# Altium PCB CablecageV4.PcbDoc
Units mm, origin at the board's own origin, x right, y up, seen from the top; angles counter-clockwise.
Board outline 44.5 x 40.08 mm, 2 copper layers (Top Layer, Bottom Layer); 20 components, 28 nets, 91 pads, 70 vias.
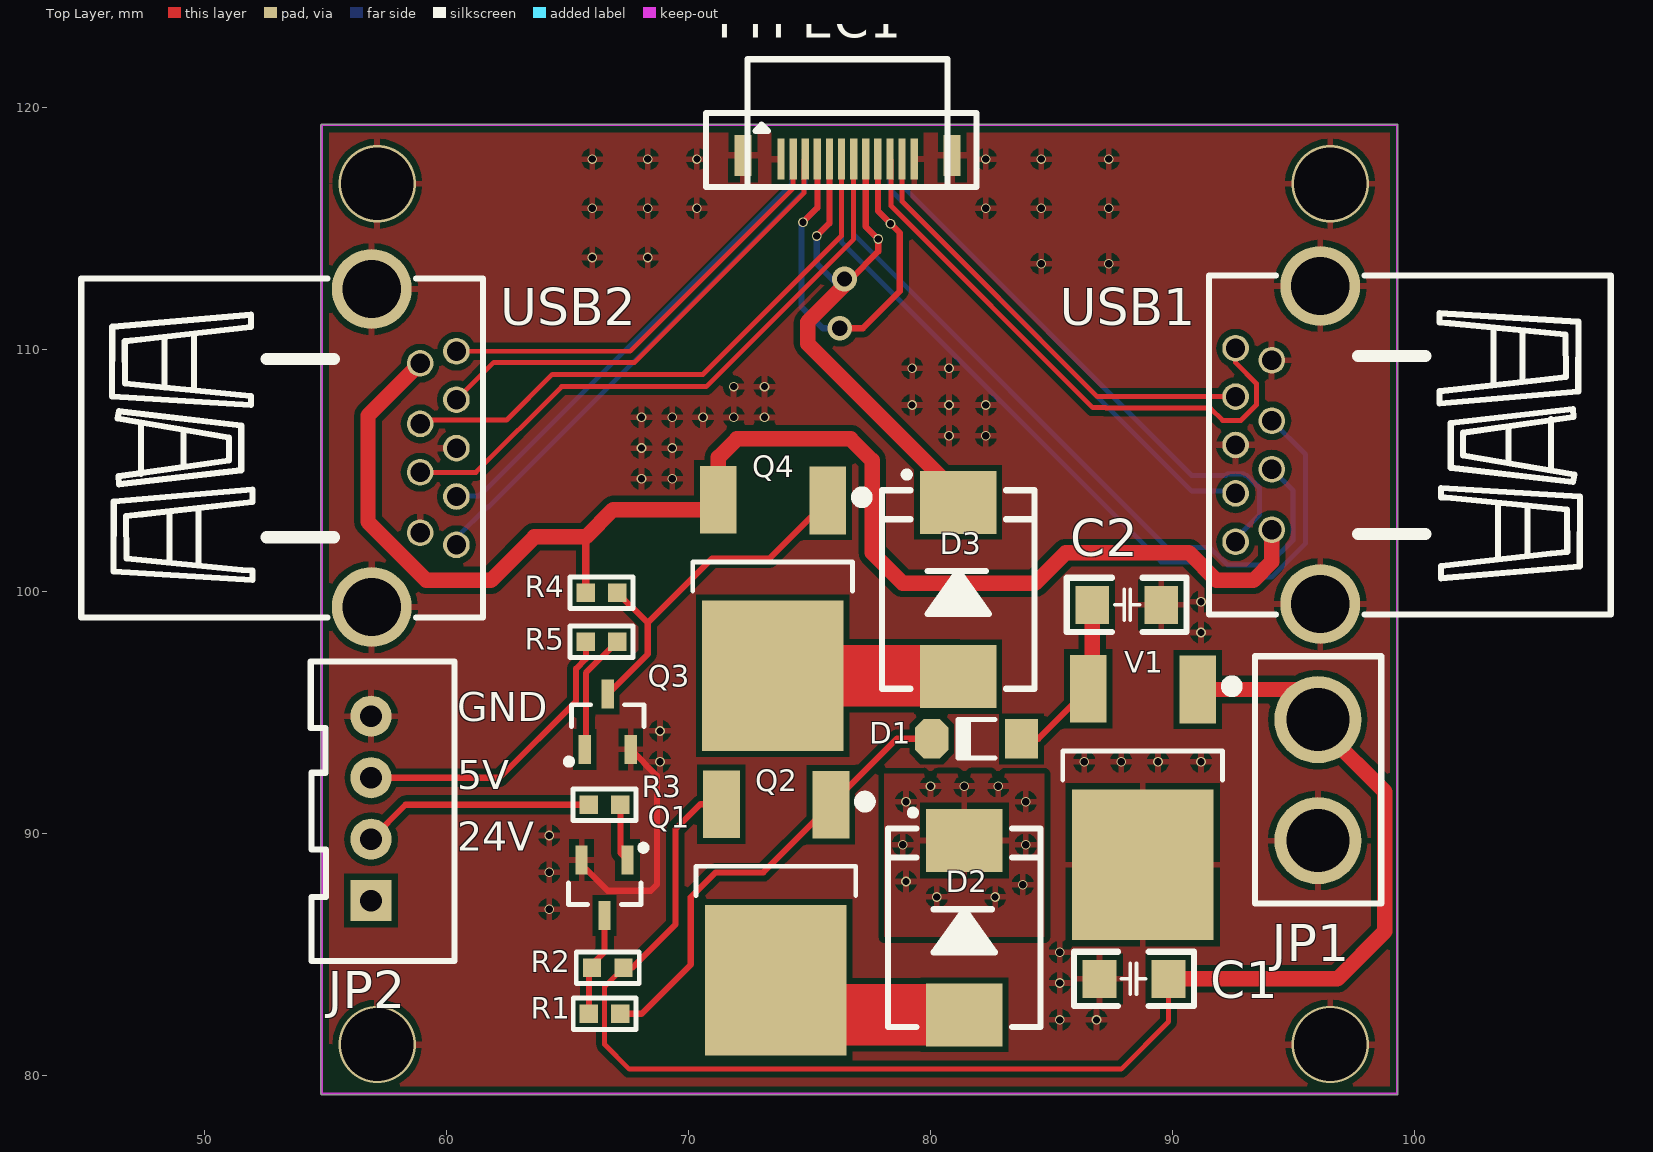
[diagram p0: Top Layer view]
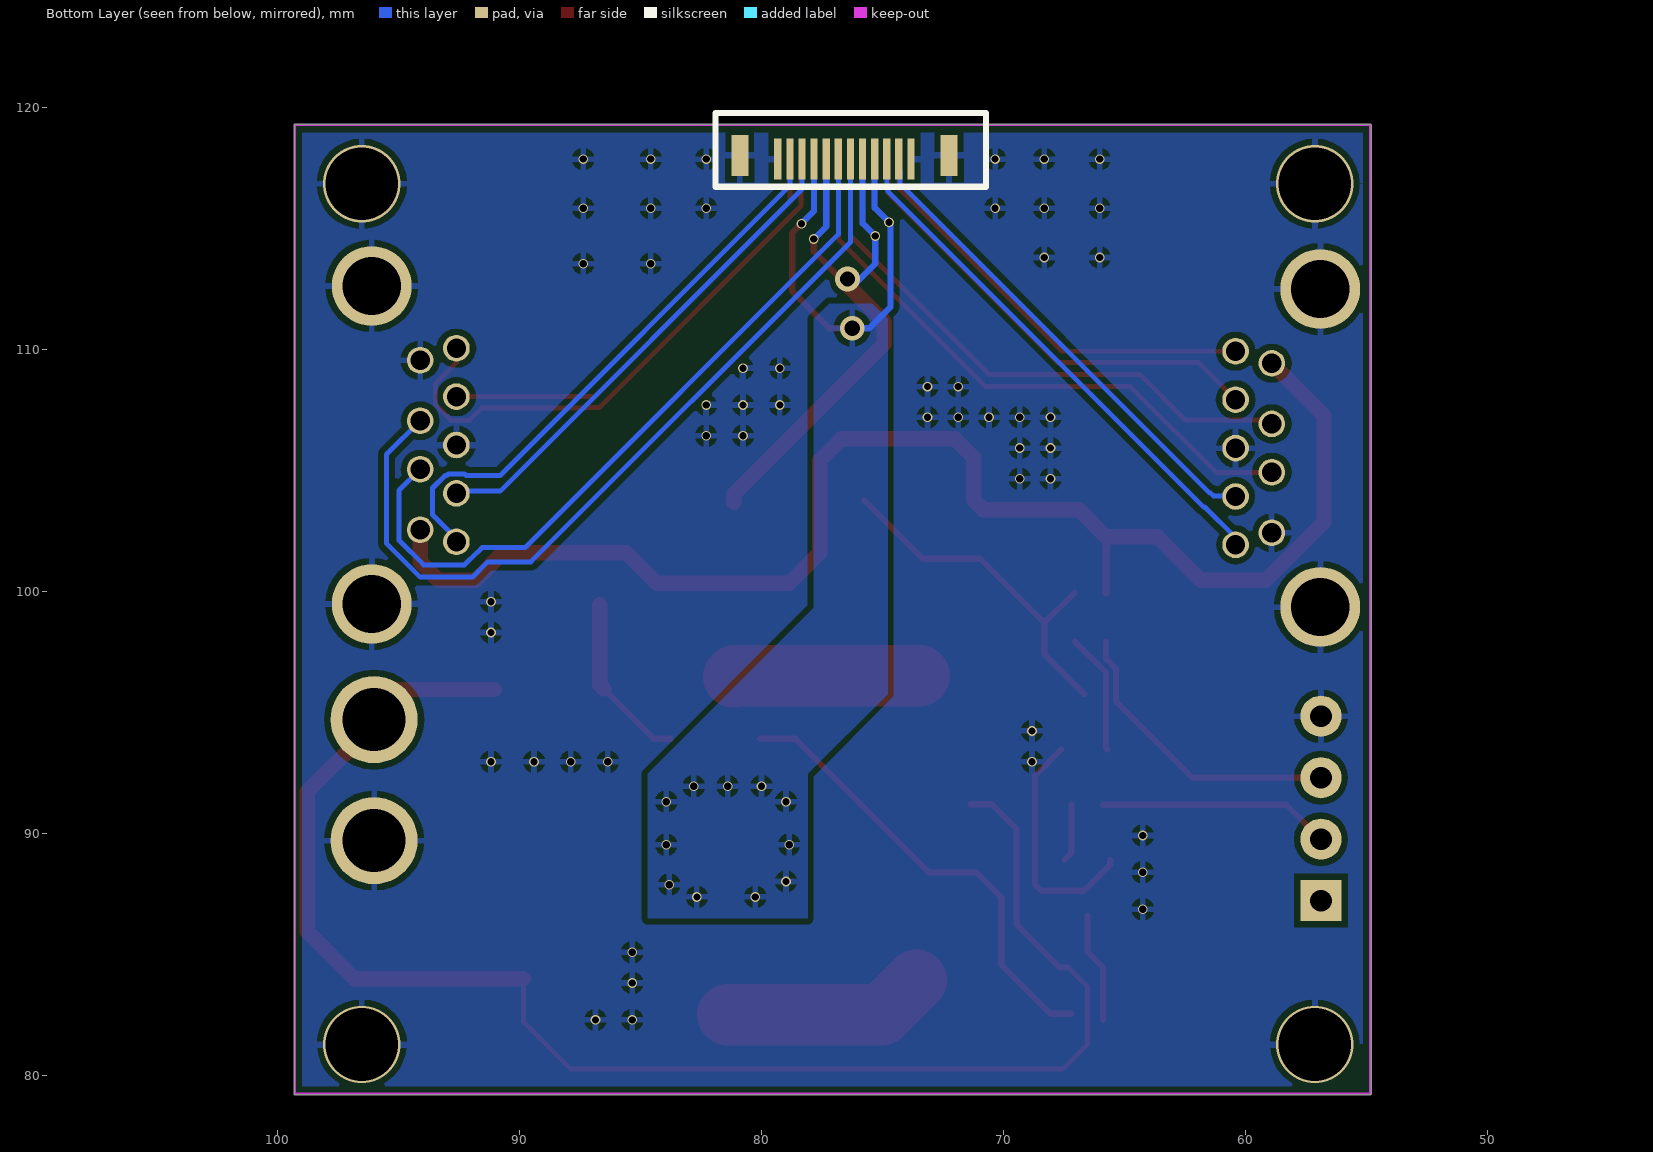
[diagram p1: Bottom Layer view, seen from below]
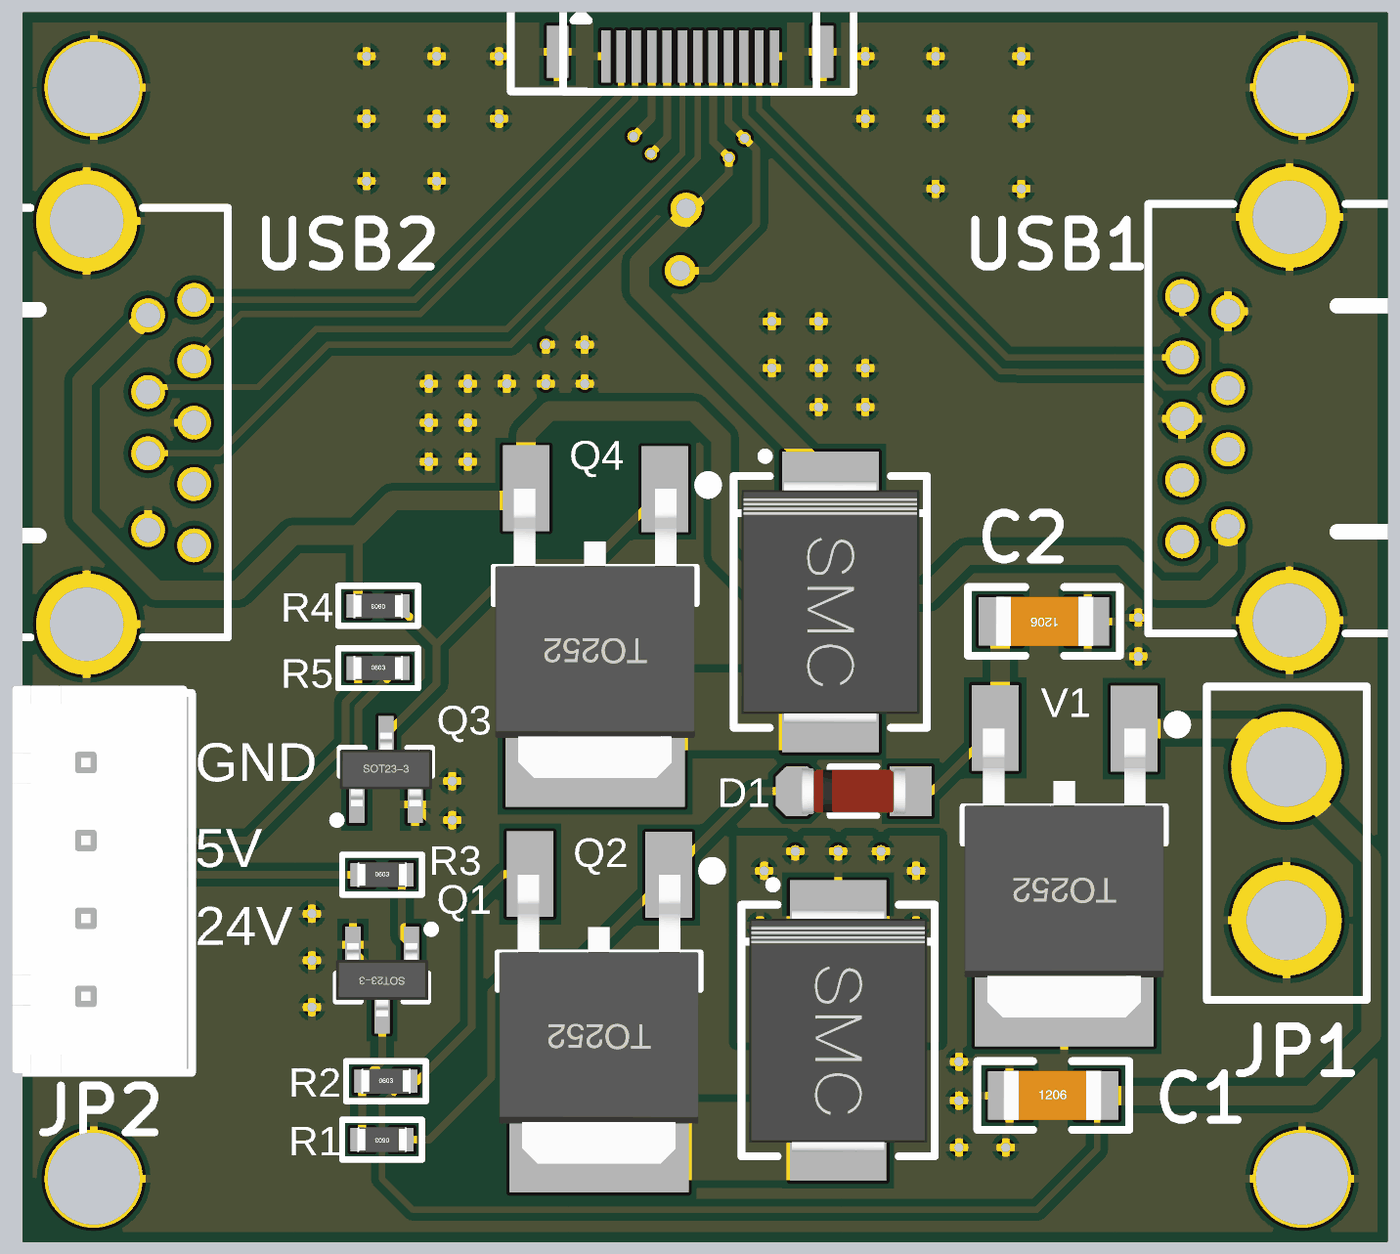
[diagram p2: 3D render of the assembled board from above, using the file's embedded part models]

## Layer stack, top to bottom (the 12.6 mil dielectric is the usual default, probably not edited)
Top Solder: solder mask 0.0102, Solder Resist, Dk 3.5
Top Layer: signal copper 0.0356
Dielectric 1: dielectric 0.32, FR-4, Dk 4.8
Bottom Layer: signal copper 0.0356
Bottom Solder: solder mask 0.0102, Solder Resist, Dk 3.5

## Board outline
54.864,79.21 cw(c54.864,79.248) 54.826,79.248 54.826,119.253 cw(c54.864,119.253) 54.864,119.291 99.282,119.291 cw(c99.282,119.253) 99.321,119.253 99.321,79.248 cw(c99.282,79.248) 99.282,79.21

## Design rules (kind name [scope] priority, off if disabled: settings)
Clearance [All] p1: gap=0.152 ignorepadtopadclearanceinfootprint=TRUE except(0: Arc-Hole Track-Hole SMDPad-Hole THPad-Hole Via-Hole Fill-Hole Poly-Hole Region-Hole Text-Hole; 0.254: Arc-Fill Arc-Poly Arc-Region Track-Fill Track-Poly Track-Region SMDPad-Fill SMDPad-Poly SMDPad-Region THPad-Fill THPad-Poly THPad-Region Via-Fill Via-Poly Via-Region Fill-Fill Fill-Poly Fill-Region Poly-Poly Poly-Region Region-Region)
DiffPairsRouting [All] p1: maxlimit=0.508 minlimit=0.254 mostfreqgap=0.381 toplayer_minwidth=0.152 toplayer_maxwidth=0.635 toplayer_prefwidth=0.381 bottomlayer_minwidth=0.152 bottomlayer_maxwidth=0.635 bottomlayer_prefwidth=0.381 maxuncoupledlength=12.7
PolygonConnect [All] p1: connectstyle=Relief reliefconductorwidth=0.254 reliefentries=4 polygonreliefangle="90 Angle" airgapwidth=0.254
RoutingVias [All] p1: holewidth=0.711 width=1.27 viastyle="Through Hole" minholewidth=0.711 minwidth=1.27 maxholewidth=0.711 maxwidth=1.27
SolderMaskExpansion [All] p1: expansion=0.102
Width [All] p1: maxlimit=2.54 minlimit=0.152 preferedwidth=0.254 minimp=50.000000 maximp=50.000000 favimp=50.000000
29 further rules are at their usual default settings.

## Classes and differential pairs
differential pair D4: +D4_P -D4_N
differential pair USB3-T: +USB3-T_P -USB3-T_N
differential pair USB3-T2: +USB3-T2_P -USB3-T2_N
differential pair USB3-R: +USB3-R_P -USB3-R_N
differential pair USB3-R2: +USB3-R2_P -USB3-R2_N
differential pair D3: +D3_P -D3_N

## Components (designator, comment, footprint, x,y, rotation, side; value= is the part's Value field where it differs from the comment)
C1 "104" "C 1206_L" 88.392,83.991 r0 top
C2 "104" "C 1206_L" 88.138,99.441 r180 top
D1 "1N4148" "MINI_MELF (LL34)" 81.915,93.909 r180 top
D2 "SS34" SMC 81.407,86.106 r90 top
D3 "SS34" SMC 81.153,100.076 r90 top
JP1 "HDR-1X2" XT30 96.012,92.202 r270 top
JP2 "HDR-1X4" XH2.54-LI-4P 56.896,91.032 r90 top
Q1 "SI2302" SOT23-3N 66.548,87.757 r180 top
Q2 "IRF540" TO252 73.616,88.138 r180 top
Q3 "SI2302" SOT23-3N 66.675,94.615 r0 top
Q4 "IRF540" TO252 73.489,100.711 r180 top
R1 "1K" "R 0603_L" 66.548,82.55 r180 top
R2 "1K" "R 0603_L" 66.675,84.455 r0 top
R3 "1K" "R 0603_L" 66.548,91.186 r0 top
R4 "1K" "R 0603_L" 66.421,99.949 r180 top
R5 "1K" "R 0603_L" 66.421,97.917 r0 top
TYPEC1 "USB31-TYPEC-33141-2FS" TYPEC-CHABAN24P 76.581,116.713 r90 top
USB1 "FUS301-FDBU1K" USB3.0-A-TH_FUS301-FDBU1K 94.361,106.045 r90 top
USB2 "FUS301-FDBU1K" USB3.0-A-TH_FUS301-FDBU1K 58.674,105.918 r270 top
V1 "78xx" TO252 88.773,92.903 r180 top

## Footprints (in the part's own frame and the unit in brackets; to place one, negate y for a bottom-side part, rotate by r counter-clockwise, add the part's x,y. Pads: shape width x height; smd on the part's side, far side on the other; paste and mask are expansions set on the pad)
"C 1206_L" [mil] "无极性贴片电容"
  rect 55x62 smd: 1(-55.12,0) 2(57.09,0)
  silkscreen extent -96,-44 98,44, body extent -63,-32 63,32, height 48
"MINI_MELF (LL34)" [mm] "1.5*3.4mm(直径，脚距）"
  rect 1.37x1.62 smd: 1(-1.855,0)
  oct 1.37x1.62 smd: 2(1.855,0)
  silkscreen extent -0.76,-0.8 0.78,0.8, body extent -1.7,-0.75 1.7,0.75, height 1.5
"R 0603_L" [mil] "1/10W贴片电阻                 淘宝ID:黄晶宝石"
  rect 30x30 smd: 1(-25.59,0) 2(25.59,0)
  silkscreen extent -51,-26 51,26, body extent -31,-16 32,16, height 16
SMC [mm] "7.1x5.9*2.3mm（长宽高，不包括引脚）"
  rect 2.6x3.15 smd: 1(-3.6,0) 2(3.6,0)
  silkscreen extent -4.1,-3.15 4.87,3.15, body extent -3.95,-2.9 3.95,2.9, height 2.45
SOT23-3N [mm] "3x1.3x1mm(长宽高)    封装库来自淘宝卖家 ID：黄晶宝石"
  rect 0.5x1.2 smd: 1(-0.95,-1.143) 2(0.95,-1.143) 3(0,1.143)
  silkscreen extent -1.73,-1.78 1.5,0.7, body extent -1.5,-1.2 1.5,1.2, height 1.05
TO252 [mil] "252晶体管"
  rect 60x110 smd: 1(-89.55,-119.77) 3(88.45,-120.77)
  rect 230x245 smd: 2(0,165.35)
  silkscreen extent -153,-133 130,28, body extent -128,-120 128,251, height 91
TYPEC-CHABAN24P [mm]
  rect 1.7x0.7 smd: 0(1.293,4.317) 0(1.293,-4.323)
  rect 1.7x0.7 smd far side: 0(1.293,4.317) 0(1.293,-4.323)
  rect 1.7x0.3 smd: A1(1.143,2.747) A2(1.143,2.248) A3(1.143,1.748) A4(1.143,1.247) A5(1.143,0.746) A6(1.143,0.247) A7(1.143,-0.253) A8(1.143,-0.752) A9(1.143,-1.252) A10(1.143,-1.751) A11(1.143,-2.252) A12(1.143,-2.753)
  rect 1.7x0.3 smd far side: B1(1.143,-2.753) B2(1.143,-2.253) B3(1.143,-1.753) B4(1.143,-1.254) B5(1.143,-0.754) B6(1.143,-0.254) B7(1.143,0.247) B8(1.143,0.748) B9(1.143,1.248) B10(1.143,1.748) B11(1.143,2.247) B12(1.143,2.747)
  silkscreen extent -0.01,-5.33 5.27,5.84
USB3.0-A-TH_FUS301-FDBU1K [mm]
  round 1.1 hole 0.8: 1(-3.5,0.25) 2(-1,0.25) 3(1,0.25) 4(3.5,0.25) 5(4,1.75) 6(2,1.75) 7(0,1.75) 8(-2,1.75) 9(-4,1.75)
  round 3.3 hole 2.4: 10(-6.57,-1.75) 10(6.57,-1.75)
  silkscreen extent -7,-13.75 7,2.85
XH2.54-LI-4P [mm] "接插件，4P  淘宝ID:黄晶宝石   店铺网址:https://shop463601444.taobao.com"
  rect 1.7x1.7 hole 0.9: 1(-3.81,0)
  round 1.7 hole 0.9: 2(-1.27,0) 3(1.27,0) 4(3.81,0)
  silkscreen extent -6.3,-3.45 6.07,2.49, body extent -6.31,-3.3 6.31,2.4, height 7.03
XT30 [mm]
  round 3.6 hole 2.6: 1(-2.5,0) 2(2.5,0)
  silkscreen extent -5.12,-2.59 5.09,2.62

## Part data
C1 C2: library part C, "贴片电容"
D1: "开关二极管"
D2 D3: "肖特基二极管"
JP1: library part "Header 2", "2P接插件"
JP2: library part "Header 4", "4P接插件"
Q1 Q3: "N沟道场效应管"
Q2 Q4: "P沟场效应管"
R1 R2 R3 R4 R5: library part R, "贴片电阻"
TYPEC1: BOM_JLCPCB Part Class="Extended Part", BOM_Manufacturer="XKB Enterprise"
USB1 USB2: BOM_JLCPCB Part Class="Extended Part", BOM_Manufacturer=TXGA
V1: "线性稳压芯片"

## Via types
v1: diameter 0.4, hole 0.3, Top Layer to Bottom Layer, 64 vias
v2: diameter 3.2, hole 3, Top Layer to Bottom Layer, 4 vias
v3: diameter 1.016, hole 0.635, Top Layer to Bottom Layer, 2 vias

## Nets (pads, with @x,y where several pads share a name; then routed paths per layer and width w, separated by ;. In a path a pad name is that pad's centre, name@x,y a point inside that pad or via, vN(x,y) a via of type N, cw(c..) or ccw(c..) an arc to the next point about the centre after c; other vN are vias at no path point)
3V3: JP2.1
5.0V: D3.2 TYPEC1.A5 TYPEC1.A8 TYPEC1.B5 TYPEC1.B8 | length 31.4
  Top Layer w0.254: v1(75.311,114.681) 75.835,115.205 TYPEC1.A5 ; v3(76.454,112.903) 76.708,112.903 77.851,114.046 v1(77.851,114.554) 77.333,115.072 TYPEC1.A8
  Top Layer w0.635: v3(76.454,112.903) 76.454,112.649 74.93,111.125 74.93,110.236 81.153,104.013 D3.2
  Bottom Layer w0.254: TYPEC1.B8 75.833,115.203 v1(75.311,114.681) 75.311,113.538 76.2,112.649 v3(76.454,112.903) ; TYPEC1.B5 77.335,115.07 v1(77.851,114.554)
5V: Q4.3 R4.2 USB1.1 USB2.1 | length 58.9
  Top Layer w0.305: R4.2 65.771,102.25
  Top Layer w0.635: USB2.1 56.769,107.263 56.769,102.87 59.182,100.457 61.849,100.457 63.642,102.25 65.771,102.25 66.899,103.378 70.842,103.378 Q4.3 71.242,105.532 72.009,106.299 76.708,106.299 77.597,105.41 77.597,101.6 78.867,100.33 84.328,100.33 85.598,101.6 90.678,101.6 91.821,100.457 93.345,100.457 94.111,101.223 USB1.1
9V: C2.2 D1.1 V1.3 | length 7.1
  Top Layer w0.254: D1.1 84.464,93.909 V1.3
  Top Layer w0.635: V1.3 86.688,96.132 C2.2
24V: C1.2 JP1.1 Q2.3 R2.2 V1.1 | length 64.2
  Top Layer w0.203: R2.2 66.548,83.678 66.548,81.28 67.564,80.264 87.884,80.264 89.842,82.222 C1.2
  Top Layer w0.254: R2.2 67.691,84.455 69.469,86.233 69.469,90.17 70.505,91.206 Q2.3
  Top Layer w0.635: C1.2 96.818,83.991 98.774,85.947 98.774,91.726 96.393,94.107 96.393,94.575 95.023,95.945 V1.1
D3_N: TYPEC1.A7 USB2.3 | length 25.2
  Top Layer w0.203: USB2.3 61.228,104.918 64.768,108.458 70.739,108.458 76.834,114.553 TYPEC1.A7
D3_P: TYPEC1.A6 USB2.2 | length 23.8
  Top Layer w0.203: USB2.2 59.084,107.078 62.501,107.078 64.389,108.966 70.612,108.966 76.334,114.688 TYPEC1.A6
D4_N: TYPEC1.B7 USB1.3 | length 34.6
  Bottom Layer w0.203: TYPEC1.B7 76.334,114.42 89.535,101.219 91.313,101.219 91.948,100.584 94.107,100.584 95.504,101.981 95.504,105.652 USB1.3
D4_P: TYPEC1.B6 USB1.2 | length 30.6
  Bottom Layer w0.203: TYPEC1.B6 76.835,114.745 89.777,101.803 91.555,101.803 91.758,101.6 91.77,101.6 92.278,101.092 93.968,101.092 94.984,102.108 94.984,104.172 USB1.2
GATE_5V: Q3.3 Q4.1 R4.1 | length 14.9
  Top Layer w0.254: Q3.3 68.326,97.409 68.326,98.694 ; R4.1 68.326,98.694 ; Q4.1 73.356,101.346 70.978,101.346 68.326,98.694
GATE_24V: D1.2 Q2.1 R1.1 | length 19.2
  Top Layer w0.254: R1.1 68.072,82.55 70.104,84.582 70.104,87.361 71.135,88.392 73.102,88.392 Q2.1 78.619,93.909 D1.2
GND: C1.1 C2.1 JP1.2 JP2.4 Q1.2 Q3.2 TYPEC1.0 TYPEC1.A1 TYPEC1.A12 TYPEC1.B1 TYPEC1.B12 USB1.4 USB1.7 USB1.10 USB2.4 USB2.7 USB2.10 V1.2 | length 9.9
  Top Layer w0.254: Q1.2 65.598,88.707 66.675,87.63 68.453,87.63 68.707,87.884 68.707,92.39 Q3.2
  other v1: 85.344,82.296 86.868,82.296 85.344,83.82 85.344,85.09 64.262,86.868 64.262,88.392 64.262,89.916 68.834,92.964 86.36,92.964 87.884,92.964 89.408,92.964 91.186,92.964 68.834,94.234 91.186,98.298 91.186,99.568 68.072,104.648 69.342,104.648 68.072,105.918 69.342,105.918 80.772,106.426 82.296,106.426 68.072,107.188 69.342,107.188 70.612,107.188 71.882,107.188 73.152,107.188 79.248,107.696 80.772,107.696 82.296,107.696 71.882,108.458 73.152,108.458 79.248,109.22 80.772,109.22 84.582,113.538 87.376,113.538 66.04,113.792 68.326,113.792 66.04,115.824 68.326,115.824 70.358,115.824 82.296,115.824 84.582,115.824 87.376,115.824 66.04,117.856 68.326,117.856 70.358,117.856 82.296,117.856 84.582,117.856 87.376,117.856
  other v2: 57.15,81.28 96.52,81.28 57.15,116.84 96.52,116.84
NetD2_1: D2.1 Q2.2 | length 8.4
  Top Layer w2.54: Q2.2 75.048,82.506 D2.1
NetD3_1: D3.1 Q4.2 | length 7.7
  Top Layer w2.54: Q4.2 81.118,96.511 D3.1
NetQ1_1: Q1.1 R3.2 | length 2.4
  Top Layer w0.254: R3.2 67.198,89.2 Q1.1
NetQ1_3: Q1.3 R1.2 R2.1 | length 4.6
  Top Layer w0.254: R1.2@65.898,82.296 65.898,84.455 66.548,85.105 Q1.3
NetQ3_1: Q3.1 R5.2 | length 5
  Top Layer w0.254: Q3.1 65.771,93.518 65.771,96.632 R5.2@67.063,97.924
USB3-R2_N: TYPEC1.A10 USB1.5 | length 23.7
  Top Layer w0.203: TYPEC1.A10 78.376,117.812 78.376,115.923 86.711,107.588 87.249,107.588 87.249,107.569 91.567,107.569 92.075,107.061 92.837,107.061 93.472,107.696 93.472,108.585 92.611,109.446 USB1.5
USB3-R2_P: TYPEC1.A11 USB1.6 | length 18.9
  Top Layer w0.203: TYPEC1.A11 78.833,116.112 86.9,108.045 USB1.6
USB3-R_N: TYPEC1.B10 USB2.5 | length 21.9
  Bottom Layer w0.203: USB2.5 60.424,102.207 61.706,103.489 61.757,103.489 74.791,116.523 74.791,116.574 74.833,116.616 TYPEC1.B10
USB3-R_P: TYPEC1.B11 USB2.6 | length 20.3
  Bottom Layer w0.203: USB2.6 60.424,103.946 61.337,103.946 61.464,104.073 61.515,104.073 74.295,116.853 74.295,117.357 74.334,117.395 TYPEC1.B11
USB3-T2_N: TYPEC1.B3 USB1.8 | length 20.7
  Bottom Layer w0.203: TYPEC1.B3 78.334,116.611 90.805,104.14 92.516,104.14 USB1.8
USB3-T2_P: TYPEC1.B2 USB1.9 | length 23.7
  Bottom Layer w0.203: TYPEC1.B2 78.834,116.757 90.811,104.781 92.21,104.781 92.278,104.849 92.944,104.849 93.012,104.781 93.085,104.781 93.599,104.267 93.599,103.17 92.611,102.182 USB1.9
USB3-T_N: TYPEC1.A3 USB2.8 | length 19.3
  Top Layer w0.203: USB2.8 61.967,109.461 67.79,109.461 74.79,116.461 74.79,117.814 TYPEC1.A3
USB3-T_P: TYPEC1.A2 USB2.9 | length 17.9
  Top Layer w0.203: USB2.9 67.601,109.918 74.333,116.65 TYPEC1.A2
VCC: D2.2 TYPEC1.A4 TYPEC1.A9 TYPEC1.B4 TYPEC1.B9 | length 23
  Top Layer w0.254: v1(74.739,115.252) 75.334,115.847 TYPEC1.A4 ; v3(76.263,110.871) 77.216,110.871 78.74,112.395 78.74,114.808 v1(78.359,115.189) 77.833,115.715 TYPEC1.A9
  Bottom Layer w0.254: TYPEC1.B9 75.333,115.846 v1(74.739,115.252) 74.676,115.189 74.676,111.76 75.565,110.871 v3(76.263,110.871) ; TYPEC1.B4 77.835,115.713 v1(78.359,115.189)
  other v1: 80.264,87.376 82.677,87.376 83.82,87.884 78.994,88.011 78.867,89.535 83.947,89.535 78.994,91.313 83.947,91.313 80.01,91.948 81.407,91.948 82.804,91.948
WAKE_5V: JP2.3 R5.1 | length 12.4
  Top Layer w0.254: JP2.3 62.203,92.302 65.365,95.464 65.365,96.8 65.771,97.207 R5.1
WAKE_24V: JP2.2 R3.1 | length 9.6
  Top Layer w0.254: JP2.2 58.32,91.186 R3.1

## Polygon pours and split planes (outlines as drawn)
GND on Top Layer "GND_L01_P006" (solid, remove dead copper, pour order 6): 54.864,119.253 54.864,79.248 55.118,79.502 99.282,79.248 99.282,119.253
VCC on Top Layer "VCC_L01_P000" (solid, remove dead copper, pour order 0): 78.105,92.456 78.105,85.725 84.709,85.725 84.709,92.456
GND on Bottom Layer "GND_L02_P004" (solid, remove dead copper, pour order 4): 54.864,119.253 54.864,79.248 99.282,79.248 99.282,119.253
VCC on Bottom Layer "VCC_L02_P002" (solid, remove dead copper, pour order 2): 78.105,92.456 78.105,86.487 84.709,86.487 84.709,92.456 77.851,99.314 77.851,111.252 77.216,111.887 75.438,111.887 74.803,111.252 74.803,95.758

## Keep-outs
Keep-Out Layer:
  lines w0.076: 54.864,79.248 99.282,79.248 99.282,119.253 54.864,119.253 54.864,79.248

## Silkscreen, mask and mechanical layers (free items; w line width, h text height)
Top Overlay:
  text "GND" at 60.452,94.234 h2.03
  text "5V" at 60.452,91.44 h2.03
  text "24V" at 60.452,88.9 h2.03

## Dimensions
54.864,79.248 to 54.864,119.253 on Mechanical 15
54.864,79.248 to 99.282,79.248 on Mechanical 15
